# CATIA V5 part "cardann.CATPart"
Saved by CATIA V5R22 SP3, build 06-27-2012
Part number: User Library-Universal Joint222_Universal Joint222Part1
Revision: ANY
Definition: UNKNOWN
Nomenclature: User Library-Universal Joint222_Universal Joint222Part1
Source: Unknown
Bounding box of the stored display mesh (mm): x -50.8 to 50.8, y -38.1 to 38.1, z -19.05 to 19.05
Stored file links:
  C:\Users\PARTST~1\AppData\Local\Temp\WF6552.tmp\User Library-Universal Joint222_Universal Joint222Part1.CATPart
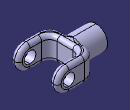
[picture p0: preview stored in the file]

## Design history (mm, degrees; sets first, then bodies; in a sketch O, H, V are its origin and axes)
Body1 "CirPattern1" (main body)
  Solid1: solid without history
